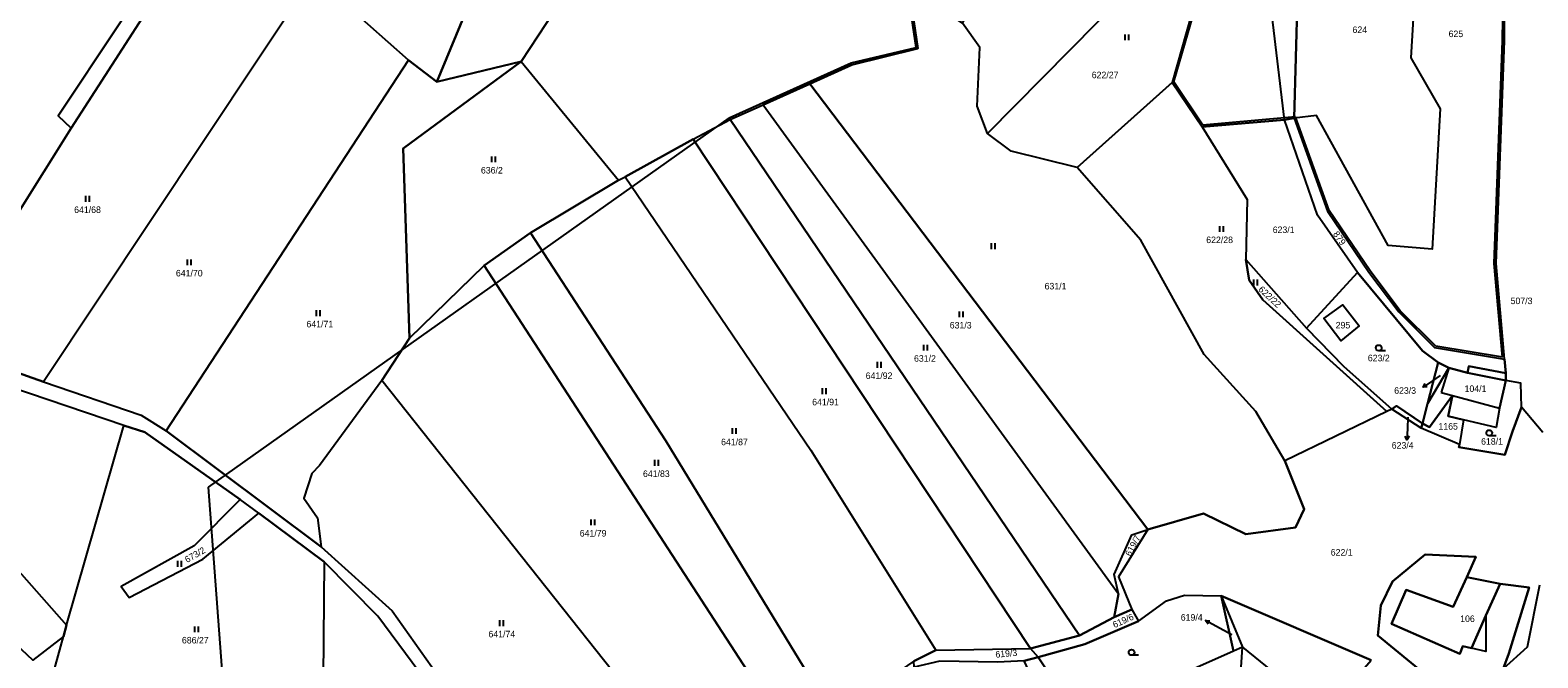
# Model space of a CAD drawing. Extents: x -654083 to -650132, y -1099819 to -1096699.
# Drawn here: x -652143 to -651750.7, y -1098980.8 to -1098817.7 of the extents above; entities that cross this region are included whole.
import ezdxf

# ---------------------------------------------------------------- set-up
doc = ezdxf.new("R2010")
doc.units = 0
for name, color, linetype in [('Hranice - vnitř_ kresba', 7, 'Continuous'), ('Obvody jako plochy', 7, 'Continuous'), ('Ostatní hranice', 7, 'Continuous'), ('Parcelní čísla', 7, 'Continuous'), ('Prvky pro prodl_ par_ č_', 7, 'Continuous'), ('Značky kultur', 7, 'Continuous')]:
    doc.layers.add(name, color=color, linetype=linetype)

msp = doc.modelspace()

# ---------------------------------------------------------------- linework, layer by layer
at = {"layer": 'Hranice - vnitř_ kresba'}
for p, q in [((-651773.93, -1098905.49), (-651775.89, -1098911.85)), ((-651769, -1098906.72), (-651759.1, -1098908.72)), ((-651775.89, -1098911.85), (-651772.92, -1098912.64)), ((-651772.92, -1098912.64), (-651760.67, -1098915.89)), ((-651764.31, -1098969.81), (-651767.96, -1098978.35))]:
    msp.add_line(p, q, dxfattribs=at)
at = {"layer": 'Obvody jako plochy'}
for points in [[(-651749.46, -1098922.3), (-651754.98, -1098915.64), (-651755.14, -1098909.42), (-651759.1, -1098908.72), (-651759.05, -1098906.84), (-651759.39, -1098903.24), (-651761.61, -1098878.37), (-651759.39, -1098820.46), (-651758.87, -1098743.54), (-651758.78, -1098730.71), (-651758.16, -1098645.99), (-651759.08, -1098493.26), (-651759.13, -1098479.91), (-651747.5, -1098480.08)], [(-651997.87, -1098799.37), (-652015.21, -1098825.87), (-651989.91, -1098856.67), (-651988.2, -1098855.79), (-651970.48, -1098846.02), (-651960.85, -1098840.94), (-651952.25, -1098837.06), (-651940.1, -1098831.66), (-651929.23, -1098826.66), (-651912.07, -1098822.45), (-651914.35, -1098806.58)], [(-651840.82, -1098813.57), (-651845.87, -1098831.26), (-651838.1, -1098842.79), (-651816.61, -1098840.96), (-651820.78, -1098806.04)], [(-652036.36, -1098991.75), (-652052.55, -1098970.01), (-652066.5, -1098955.88), (-652083.44, -1098943.2), (-652088.35, -1098939.68), (-652113.16, -1098922.18), (-652118.61, -1098920.4), (-652177.75, -1098900.4)], [(-652167.51, -1098899.22), (-652139.47, -1098909.11), (-652114.09, -1098917.71), (-652107.61, -1098921.8), (-652067.27, -1098951.96), (-652048.76, -1098968.58), (-652035.5, -1098987.36)], [(-651749.46, -1098922.3), (-651754.98, -1098915.64), (-651757.33, -1098921.99), (-651759.33, -1098928.07), (-651771.25, -1098926.07), (-651771.13, -1098925.34), (-651781.13, -1098921.09), (-651788.75, -1098916.15), (-651790.05, -1098916.78), (-651816.53, -1098929.59), (-651811.56, -1098942.21), (-651813.78, -1098946.97), (-651826.72, -1098948.65), (-651837.69, -1098943.35), (-651852.21, -1098947.49), (-651859.84, -1098959.78), (-651856.39, -1098968.25), (-651854.67, -1098971.29), (-651847.31, -1098966.04), (-651842.68, -1098964.55), (-651833.16, -1098964.69), (-651794.08, -1098981.46)], [(-651779.36, -1098985.7), (-651792.39, -1098975.02), (-651791.56, -1098967.26), (-651788.54, -1098961), (-651780.08, -1098953.99), (-651766.9, -1098954.58), (-651769.24, -1098959.9), (-651760.5, -1098961.58), (-651752.98, -1098962.53), (-651758.27, -1098979.71), (-651759.73, -1098983.72), (-651753.42, -1098977.94), (-651750.25, -1098961.84)], [(-651759.73, -1098983.72), (-651753.42, -1098977.94), (-651750.25, -1098961.84)]]:
    msp.add_lwpolyline(points, dxfattribs=at)
for points in [[(-651997.06, -1098783.64), (-651997.87, -1098799.37), (-652015.21, -1098825.87), (-652037.14, -1098831.11), (-652012.42, -1098771.38), (-652016.3, -1098762.42), (-652004.62, -1098728.93), (-652019.93, -1098708.7), (-652031.6, -1098704.7), (-652032.96, -1098702.66), (-652016.1, -1098650.33), (-652014.41, -1098650.46), (-651976.85, -1098658.9), (-651966.03, -1098663.49), (-651947.18, -1098696.04), (-651957.54, -1098717), (-651971.47, -1098740.14), (-651965.9, -1098771.25), (-651988.55, -1098777.75)], [(-652019.93, -1098708.7), (-652004.62, -1098728.93), (-652016.3, -1098762.42), (-652012.42, -1098771.38), (-652037.14, -1098831.11), (-652044.51, -1098825.49), (-652060.42, -1098811.42), (-652068.91, -1098801.82), (-652040.98, -1098718.29), (-652037.58, -1098702.43), (-652031.6, -1098704.7)], [(-651814.1, -1098840.59), (-651816.61, -1098840.96), (-651820.78, -1098806.04), (-651826.77, -1098790.4), (-651809.7, -1098770.47), (-651794.82, -1098727.22), (-651787.37, -1098732.09), (-651802.28, -1098762.68), (-651817.26, -1098801.09), (-651813.22, -1098808.91)], [(-651783.79, -1098824.89), (-651776.17, -1098838.14), (-651778.27, -1098874.59), (-651789.69, -1098873.67), (-651808.31, -1098839.89), (-651814.1, -1098840.59), (-651813.22, -1098808.91), (-651817.26, -1098801.09), (-651802.28, -1098762.68), (-651787.37, -1098732.09), (-651795.51, -1098766.45), (-651780.48, -1098769.39)], [(-651761.61, -1098878.37), (-651759.39, -1098820.46), (-651758.87, -1098743.54), (-651779.83, -1098734.91), (-651787.37, -1098732.09), (-651795.51, -1098766.45), (-651780.48, -1098769.39), (-651783.79, -1098824.89), (-651776.17, -1098838.14), (-651778.27, -1098874.59), (-651789.69, -1098873.67), (-651808.31, -1098839.89), (-651814.1, -1098840.59), (-651805.45, -1098864.76), (-651794.74, -1098880.55), (-651786.91, -1098890.92), (-651777.58, -1098900.2), (-651759.39, -1098903.24)], [(-651881.91, -1098785.73), (-651865.93, -1098788.63), (-651857.97, -1098797.16), (-651851.07, -1098801.12), (-651893.95, -1098844.58), (-651896.6, -1098837.48), (-651895.89, -1098822.21), (-651900.41, -1098815.9), (-651883.04, -1098784.67)], [(-652153.36, -1098796.07), (-652104.29, -1098792.76), (-652135.66, -1098839.99), (-652132.34, -1098843.2), (-652167.51, -1098899.22), (-652176.67, -1098896.52), (-652197.69, -1098893.37), (-652206.84, -1098889.86), (-652183.4, -1098853.92), (-652160.4, -1098812.38)], [(-652069.53, -1098803.88), (-652139.47, -1098909.11), (-652167.51, -1098899.22), (-652132.34, -1098843.2), (-652099.6, -1098792.44), (-652080.23, -1098791.12)], [(-652132.34, -1098843.2), (-652135.66, -1098839.99), (-652104.29, -1098792.76), (-652099.6, -1098792.44)], [(-652044.51, -1098825.49), (-652060.42, -1098811.42), (-652069.53, -1098803.88), (-652139.47, -1098909.11), (-652114.09, -1098917.71), (-652107.61, -1098921.8)], [(-651851.07, -1098801.12), (-651848.54, -1098802.6), (-651840.82, -1098813.57), (-651845.87, -1098831.26), (-651870.56, -1098853.34), (-651887.76, -1098849.12), (-651893.95, -1098844.58)], [(-651852.21, -1098947.49), (-651837.69, -1098943.35), (-651826.72, -1098948.65), (-651813.78, -1098946.97), (-651811.56, -1098942.21), (-651816.53, -1098929.59), (-651824.09, -1098916.77), (-651837.55, -1098901.98), (-651854.05, -1098872.26), (-651870.56, -1098853.34), (-651887.76, -1098849.12), (-651893.95, -1098844.58), (-651896.6, -1098837.48), (-651895.89, -1098822.21), (-651900.41, -1098815.9), (-651914.35, -1098806.58), (-651912.07, -1098822.45), (-651929.23, -1098826.66), (-651940.1, -1098831.66)], [(-652037.14, -1098831.11), (-652015.21, -1098825.87), (-652045.91, -1098848.42), (-652044.25, -1098897.77), (-652051.48, -1098908.71), (-652067.69, -1098930.81), (-652069.7, -1098932.89), (-652071.78, -1098939.34), (-652068.19, -1098944.43), (-652067.27, -1098951.96), (-652107.61, -1098921.8), (-652044.51, -1098825.49)], [(-652015.21, -1098825.87), (-651989.91, -1098856.67), (-652012.77, -1098870.4), (-652024.84, -1098878.82), (-652044.25, -1098897.77), (-652045.91, -1098848.42)], [(-651859.82, -1098964.22), (-651860.96, -1098959.17), (-651856.38, -1098948.84), (-651852.21, -1098947.49), (-651940.1, -1098831.66), (-651952.25, -1098837.06)], [(-651790.05, -1098916.78), (-651816.53, -1098929.59), (-651824.09, -1098916.77), (-651837.55, -1098901.98), (-651854.05, -1098872.26), (-651870.56, -1098853.34), (-651845.87, -1098831.26), (-651838.1, -1098842.79), (-651826.35, -1098861.72), (-651826.69, -1098877.3), (-651825.81, -1098882.66), (-651822.32, -1098887.74)], [(-651952.25, -1098837.06), (-651859.82, -1098964.22), (-651860.94, -1098970.23), (-651869.98, -1098974.99), (-651960.85, -1098840.94)], [(-651960.85, -1098840.94), (-651869.98, -1098974.99), (-651882.72, -1098978.39), (-651970.48, -1098846.02)], [(-651808.02, -1098865.76), (-651816.61, -1098840.96), (-651838.1, -1098842.79), (-651826.35, -1098861.72), (-651826.69, -1098877.3), (-651810.92, -1098895.18), (-651797.69, -1098880.67)], [(-651769, -1098906.72), (-651773.93, -1098905.49), (-651776.63, -1098904.04), (-651780.77, -1098901.07), (-651797.69, -1098880.67), (-651808.02, -1098865.76), (-651816.61, -1098840.96), (-651814.1, -1098840.59), (-651805.45, -1098864.76), (-651794.74, -1098880.55), (-651786.91, -1098890.92), (-651777.58, -1098900.2), (-651759.39, -1098903.24), (-651759.05, -1098906.84), (-651768.68, -1098905)], [(-651907.33, -1098978.84), (-651882.72, -1098978.39), (-651970.48, -1098846.02), (-651988.2, -1098855.79), (-651939.84, -1098926.87)], [(-651939.84, -1098926.87), (-651907.33, -1098978.84), (-651913.06, -1098981.68), (-651917.75, -1098984.88), (-651921.86, -1098988.27), (-651930.47, -1098991.27), (-651935.99, -1098992.68), (-651977.57, -1098924.42), (-652012.77, -1098870.4), (-651989.91, -1098856.67), (-651988.2, -1098855.79)], [(-652012.77, -1098870.4), (-651977.57, -1098924.42), (-651935.99, -1098992.68), (-651949.86, -1098994.27), (-652024.84, -1098878.82)], [(-651935.99, -1098992.68), (-651955.22, -1098997.58), (-651976.47, -1099003.17), (-652051.48, -1098908.71), (-652044.25, -1098897.77), (-652024.84, -1098878.82), (-651949.86, -1098994.27)], [(-651788.75, -1098916.15), (-651790.05, -1098916.78), (-651822.32, -1098887.74), (-651825.81, -1098882.66), (-651826.69, -1098877.3), (-651810.92, -1098895.18), (-651801.2, -1098905.14)], [(-651776.63, -1098904.04), (-651779.47, -1098914.78), (-651780.77, -1098919.9), (-651787.55, -1098915.32), (-651788.75, -1098916.15), (-651801.2, -1098905.14), (-651810.92, -1098895.18), (-651797.69, -1098880.67), (-651780.77, -1098901.07)], [(-651806.37, -1098892.66), (-651801.49, -1098889.09), (-651797.22, -1098894.54), (-651802.02, -1098898.42)], [(-651802.02, -1098898.42), (-651806.37, -1098892.66), (-651801.49, -1098889.09), (-651797.22, -1098894.54)], [(-651802.02, -1098898.42), (-651806.37, -1098892.66), (-651801.49, -1098889.09), (-651797.22, -1098894.54)], [(-652156.43, -1098996.68), (-652149.35, -1099002.46), (-652140.54, -1098997.91), (-652134.29, -1098975.26), (-652142.28, -1098981.46), (-652164.15, -1098960.95), (-652154.45, -1098948.78), (-652133.53, -1098972.32), (-652118.61, -1098920.4), (-652177.75, -1098900.4), (-652198.11, -1098896.74), (-652166.49, -1098927.88), (-652184.54, -1098948.92), (-652214.02, -1098964.67), (-652254.2, -1098964.34), (-652251.73, -1098967.45), (-652211.55, -1098975.91), (-652195.57, -1098986.8), (-652175.25, -1098978.23), (-652172.67, -1098996.89), (-652175.32, -1099004.71), (-652171.74, -1099009.98)], [(-651759.05, -1098906.84), (-651759.1, -1098908.72), (-651760.67, -1098915.89), (-651761.56, -1098920.99), (-651770.09, -1098918.98), (-651774.1, -1098917.99), (-651772.92, -1098912.64), (-651778.95, -1098920.91), (-651780.77, -1098919.9), (-651779.47, -1098914.78), (-651773.93, -1098905.49), (-651769, -1098906.72), (-651768.68, -1098905)], [(-651773.93, -1098905.49), (-651779.47, -1098914.78), (-651776.63, -1098904.04)], [(-651775.89, -1098911.85), (-651772.92, -1098912.64), (-651760.67, -1098915.89), (-651759.1, -1098908.72), (-651769, -1098906.72), (-651773.93, -1098905.49)], [(-651982.47, -1099006.86), (-651976.47, -1099003.17), (-652051.48, -1098908.71), (-652067.69, -1098930.81), (-652069.7, -1098932.89), (-652071.78, -1098939.34), (-652068.19, -1098944.43), (-652067.27, -1098951.96), (-652048.76, -1098968.58), (-652035.5, -1098987.36), (-652018.55, -1098998.86), (-652003.18, -1099003.88), (-651987.76, -1099005.15)], [(-651755.14, -1098909.42), (-651759.1, -1098908.72), (-651760.67, -1098915.89), (-651761.56, -1098920.99), (-651770.09, -1098918.98), (-651771.13, -1098925.34), (-651771.25, -1098926.07), (-651759.33, -1098928.07), (-651757.33, -1098921.99), (-651754.98, -1098915.64)], [(-651778.95, -1098920.91), (-651772.92, -1098912.64), (-651774.1, -1098917.99), (-651770.09, -1098918.98), (-651771.13, -1098925.34), (-651781.13, -1098921.09), (-651780.77, -1098919.9)], [(-651788.75, -1098916.15), (-651787.55, -1098915.32), (-651780.77, -1098919.9), (-651781.13, -1098921.09)], [(-652119.32, -1098962.27), (-652117.21, -1098965.13), (-652098.05, -1098955.18), (-652083.44, -1098943.2), (-652066.5, -1098955.88), (-652066.71, -1098985.91), (-652065.03, -1098990.08), (-652076.34, -1099006.56), (-652081.81, -1099014.79), (-652096.64, -1099001.52), (-652105.2, -1098993.79), (-652107.55, -1098994.88), (-652110.04, -1098995.59), (-652116.91, -1098988.78), (-652140.54, -1098997.91), (-652134.29, -1098975.26), (-652133.53, -1098972.32), (-652118.61, -1098920.4), (-652113.16, -1098922.18), (-652088.35, -1098939.68), (-652100.29, -1098951.7)], [(-652100.29, -1098951.7), (-652119.32, -1098962.27), (-652117.21, -1098965.13), (-652098.05, -1098955.18), (-652083.44, -1098943.2), (-652088.35, -1098939.68)], [(-652133.53, -1098972.32), (-652134.29, -1098975.26), (-652142.28, -1098981.46), (-652164.15, -1098960.95), (-652154.45, -1098948.78)], [(-651859.84, -1098959.78), (-651856.39, -1098968.25), (-651860.94, -1098970.23), (-651859.82, -1098964.22), (-651860.96, -1098959.17), (-651856.38, -1098948.84), (-651852.21, -1098947.49)], [(-651953.3, -1099049.2), (-651947.09, -1099044.82), (-651941.44, -1099031.87), (-652020.94, -1099002.46), (-652036.36, -1098991.75), (-652052.55, -1098970.01), (-652066.5, -1098955.88), (-652066.71, -1098985.91), (-652065.03, -1098990.08), (-652046.44, -1099028.6), (-652014.51, -1099048.85), (-652013.9, -1099053.95), (-652011.91, -1099055.96), (-652006.08, -1099075.31), (-651986.57, -1099086.63), (-651977.08, -1099091.95), (-651982.9, -1099101.91), (-651984.07, -1099103.58), (-651974.07, -1099106.19), (-651970.21, -1099097.74), (-651981.79, -1099081.32), (-651973.49, -1099071.96), (-651965.35, -1099062.79)], [(-651772.76, -1098967.53), (-651769.24, -1098959.9), (-651766.9, -1098954.58), (-651780.08, -1098953.99), (-651788.54, -1098961), (-651791.56, -1098967.26), (-651792.39, -1098975.02), (-651779.36, -1098985.7), (-651773.22, -1098990.18), (-651759.73, -1098983.72), (-651758.27, -1098979.71), (-651752.98, -1098962.53), (-651760.5, -1098961.58), (-651764.31, -1098969.81), (-651764.27, -1098979.18), (-651767.96, -1098978.35), (-651770.25, -1098977.75), (-651771.07, -1098979.77), (-651788.82, -1098971.95), (-651784.98, -1098963.18)], [(-651769.24, -1098959.9), (-651760.5, -1098961.58), (-651764.31, -1098969.81), (-651764.27, -1098979.18), (-651767.96, -1098978.35), (-651770.25, -1098977.75), (-651771.07, -1098979.77), (-651788.82, -1098971.95), (-651784.98, -1098963.18), (-651772.76, -1098967.53)], [(-651788.82, -1098971.95), (-651771.07, -1098979.77), (-651770.25, -1098977.75), (-651767.96, -1098978.35), (-651764.31, -1098969.81), (-651760.5, -1098961.58), (-651769.24, -1098959.9), (-651772.76, -1098967.53), (-651784.98, -1098963.18)], [(-651854.67, -1098971.29), (-651847.31, -1098966.04), (-651842.68, -1098964.55), (-651833.16, -1098964.69), (-651829.95, -1098979.1), (-651869.88, -1098996.85), (-651880.74, -1098980.63), (-651868.58, -1098977.31)], [(-651833.16, -1098964.69), (-651827.59, -1098978.08), (-651829.95, -1098979.1)], [(-651794.08, -1098981.46), (-651833.16, -1098964.69), (-651827.59, -1098978.08), (-651805.97, -1098995.57), (-651805.37, -1098994.97), (-651798.9, -1098986.88)], [(-651856.39, -1098968.25), (-651854.67, -1098971.29), (-651868.58, -1098977.31), (-651880.74, -1098980.63), (-651882.72, -1098978.39), (-651869.98, -1098974.99), (-651860.94, -1098970.23)], [(-651884.38, -1098981.57), (-651891.34, -1098981.93), (-651906.34, -1098981.69), (-651913.02, -1098983.26), (-651913.06, -1098981.68), (-651907.33, -1098978.84), (-651882.72, -1098978.39), (-651880.74, -1098980.63)], [(-651880.74, -1098980.63), (-651869.88, -1098996.85), (-651876.25, -1098999.08), (-651884.38, -1098981.57)], [(-651839.45, -1099005.21), (-651828.93, -1098998.76), (-651828.68, -1098994.84), (-651827.59, -1098978.08), (-651829.95, -1098979.1), (-651869.88, -1098996.85), (-651847.9, -1099005.61), (-651856.35, -1099012.08), (-651848.49, -1099008.88)], [(-651805.97, -1098995.57), (-651819.29, -1099008.95), (-651828.93, -1098998.76), (-651828.68, -1098994.84), (-651827.59, -1098978.08)]]:
    msp.add_lwpolyline(points, close=True, dxfattribs=at)
at = {"layer": 'Ostatní hranice'}
for p, q in [((-651759.89, -1098820.46), (-651759.18, -1098731.02)), ((-651912.5, -1098822.2), (-651914.8, -1098806.79)), ((-651845.4, -1098831.09), (-651840.33, -1098813.5)), ((-651762.11, -1098878.35), (-651759.89, -1098820.46)), ((-651929.41, -1098826.19), (-651912.5, -1098822.2)), ((-651961.08, -1098840.5), (-651929.41, -1098826.19)), ((-651837.85, -1098842.36), (-651845.4, -1098831.09)), ((-651813.82, -1098840.18), (-651816.67, -1098840.46)), ((-651805.01, -1098864.52), (-651813.82, -1098840.18)), ((-651961.08, -1098840.5), (-652096.67, -1098936.5)), ((-651816.67, -1098840.46), (-651837.85, -1098842.36)), ((-651794.35, -1098880.24), (-651805.01, -1098864.52)), ((-651759.94, -1098902.67), (-651762.11, -1098878.35)), ((-651786.52, -1098890.61), (-651794.35, -1098880.24)), ((-651777.29, -1098899.79), (-651786.52, -1098890.61)), ((-651759.94, -1098902.67), (-651777.29, -1098899.79)), ((-652096.67, -1098936.5), (-652085.33, -1099086.02))]:
    msp.add_line(p, q, dxfattribs=at)
at = {"layer": 'Prvky pro prodl_ par_ č_'}
for p, q in [((-651778.13, -1098908.81), (-651780.61, -1098910.5)), ((-651776.13, -1098907.45), (-651778.13, -1098908.81)), ((-651784.58, -1098918.29), (-651784.68, -1098921.2)), ((-651784.68, -1098921.2), (-651784.78, -1098924.2)), ((-651834.54, -1098972.57), (-651837.19, -1098971.16)), ((-651830.31, -1098974.81), (-651834.54, -1098972.57))]:
    msp.add_line(p, q, dxfattribs=at)
for points in [[(-651779.5, -1098910.35), (-651780.61, -1098910.5), (-651780.06, -1098909.52)], [(-651784.25, -1098923.22), (-651784.78, -1098924.2), (-651785.25, -1098923.18)], [(-651836.54, -1098972.07), (-651837.19, -1098971.16), (-651836.07, -1098971.19)]]:
    msp.add_lwpolyline(points, dxfattribs=at)
at = {"layer": 'Značky kultur'}
for p, q in [((-651858.2, -1098818.78), (-651858.2, -1098820.28)), ((-651857.18, -1098820.28), (-651857.18, -1098818.78)), ((-652022.95, -1098850.51), (-652022.95, -1098852.01)), ((-652021.93, -1098852.01), (-652021.93, -1098850.51)), ((-652128.59, -1098860.77), (-652128.59, -1098862.27)), ((-652127.57, -1098862.27), (-652127.57, -1098860.77)), ((-651833.56, -1098868.59), (-651833.56, -1098870.09)), ((-651832.54, -1098870.09), (-651832.54, -1098868.59)), ((-651892.99, -1098873.07), (-651892.99, -1098874.57)), ((-651891.96, -1098874.57), (-651891.96, -1098873.07)), ((-652102.15, -1098877.26), (-652102.15, -1098878.76)), ((-652101.12, -1098878.76), (-652101.12, -1098877.26)), ((-651824.71, -1098882.51), (-651824.71, -1098884.01)), ((-651823.69, -1098884.01), (-651823.69, -1098882.51)), ((-652068.52, -1098890.5), (-652068.52, -1098892)), ((-652067.49, -1098892), (-652067.49, -1098890.5)), ((-651901.27, -1098890.78), (-651901.27, -1098892.28)), ((-651900.24, -1098892.28), (-651900.24, -1098890.78)), ((-651910.58, -1098899.43), (-651910.58, -1098900.93)), ((-651909.56, -1098900.93), (-651909.56, -1098899.43)), ((-651790.39, -1098901.03), (-651792.14, -1098901.03)), ((-651922.63, -1098903.92), (-651922.63, -1098905.42)), ((-651921.6, -1098905.42), (-651921.6, -1098903.92)), ((-651936.92, -1098910.76), (-651936.92, -1098912.26)), ((-651935.9, -1098912.26), (-651935.9, -1098910.76)), ((-651960.32, -1098921.14), (-651960.32, -1098922.64)), ((-651959.3, -1098922.64), (-651959.3, -1098921.14)), ((-651761.62, -1098923.12), (-651763.37, -1098923.12)), ((-651980.53, -1098929.39), (-651980.53, -1098930.89)), ((-651979.51, -1098930.89), (-651979.51, -1098929.39)), ((-651997.11, -1098944.86), (-651997.11, -1098946.36)), ((-651996.08, -1098946.36), (-651996.08, -1098944.86)), ((-652104.6, -1098955.64), (-652104.6, -1098957.14)), ((-652103.58, -1098957.14), (-652103.58, -1098955.64)), ((-652100.22, -1098972.66), (-652100.22, -1098974.16)), ((-652099.2, -1098974.16), (-652099.2, -1098972.66)), ((-652020.87, -1098971.06), (-652020.87, -1098972.56)), ((-652019.84, -1098972.56), (-652019.84, -1098971.06)), ((-651854.67, -1098980.15), (-651856.42, -1098980.15))]:
    msp.add_line(p, q, dxfattribs=at)
for centre in [(-651792.14, -1098900.28), (-651763.37, -1098922.37), (-651856.42, -1098979.4)]:
    msp.add_circle(centre, 0.75, dxfattribs=at)

# ---------------------------------------------------------------- texts
at = {"layer": 'Parcelní čísla'}
for s, height, p in [('624', 1.7, (-651798.95, -1098818.43)), ('625', 1.7, (-651773.95, -1098819.49)), ('622/27', 1.7, (-651866.79, -1098830.18)), ('636/2', 1.7, (-652025.7, -1098854.94)), ('641/68', 1.7, (-652131.52, -1098865.21)), ('622/28', 1.7, (-651837, -1098873.03)), ('623/1', 1.7, (-651819.71, -1098870.42)), ('641/70', 1.7, (-652105.05, -1098881.69)), ('631/1', 1.7, (-651879.06, -1098885.07)), ('641/71', 1.7, (-652071.09, -1098894.93)), ('631/3', 1.7, (-651903.73, -1098895.22)), ('295', 1.7, (-651803.33, -1098895.21)), ('631/2', 1.7, (-651913.03, -1098903.86)), ('623/2', 1.7, (-651794.96, -1098903.74)), ('641/92', 1.7, (-651925.6, -1098908.35)), ('623/3', 0.1, (-651776.32, -1098907.45)), ('104/1', 1.7, (-651769.8, -1098911.72)), ('641/91', 1.7, (-651939.52, -1098915.19)), ('623/4', 0.1, (-651784.77, -1098918.29)), ('1165', 1.7, (-651776.59, -1098921.51)), ('641/87', 1.7, (-651963.22, -1098925.57)), ('618/1', 1.7, (-651765.5, -1098925.43)), ('641/83', 1.7, (-651983.54, -1098933.82)), ('641/79', 1.7, (-651999.99, -1098949.3)), ('622/1', 1.7, (-651804.61, -1098954.25)), ('106', 1.7, (-651770.94, -1098971.51)), ('686/27', 1.7, (-652103.49, -1098977.09)), ('641/74', 1.7, (-652023.74, -1098975.5)), ('619/4', 0.1, (-651830.47, -1098974.81))]:
    msp.add_text(s, height=height, dxfattribs=at).set_placement(p)
for s, rotation, p in [('879', 305.496, (-651804.12, -1098870.7)), ('622/22', 317.196, (-651823.59, -1098885.26)), ('619/7', 61.668, (-651856.71, -1098954.58)), ('673/2', 29.79, (-652102.13, -1098956.2)), ('619/6', 24.282, (-651860.87, -1098973.12)), ('619/3', 4.887, (-651891.79, -1098980.8))]:
    msp.add_text(s, height=1.7, rotation=rotation, dxfattribs=at).set_placement(p)
at = {"layer": 'Prvky pro prodl_ par_ č_'}
for s, p in [('507/3', (-651757.82, -1098888.89)), ('623/3', (-651788.11, -1098912.2)), ('623/4', (-651788.75, -1098926.45)), ('619/4', (-651843.63, -1098971.16))]:
    msp.add_text(s, height=1.7, dxfattribs=at).set_placement(p)

doc.saveas('drawing.dxf')
